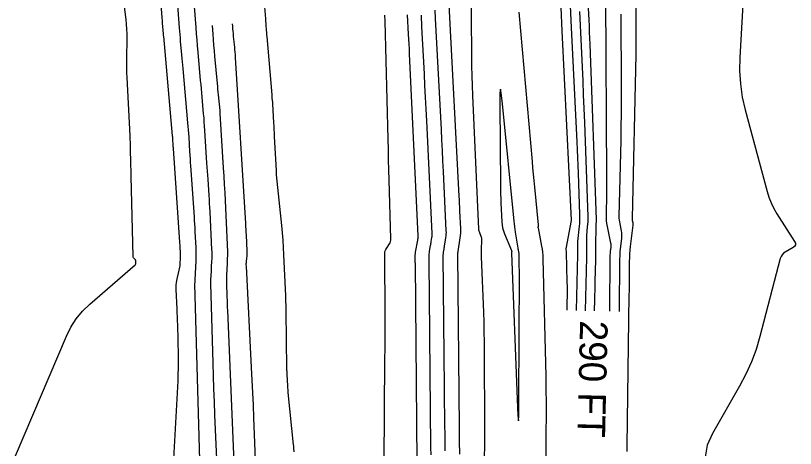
# Model space of a CAD drawing. Extents: x 1768942 to 1774819, y 723037 to 732099.
# Drawn here: x 1770723.5 to 1770892.8, y 725741.9 to 725835.9 of the extents above; entities that cross this region are included whole.
import ezdxf

# ---------------------------------------------------------------- set-up
doc = ezdxf.new("R2010")
doc.units = 0
doc.layers.add('R_Contour Annot', color=7, linetype='Continuous')
doc.layers.add('R_Contours', color=7, linetype='Continuous')

msp = doc.modelspace()

# ---------------------------------------------------------------- linework, layer by layer
at = {"layer": 'R_Contours'}
for points in [[(1770753.58, 725857.05), (1770755.22, 725835.49), (1770755.24, 725835.24), (1770755.26, 725834.98), (1770755.27, 725834.73), (1770755.29, 725834.48), (1770755.39, 725833.27), (1770755.4, 725833.11), (1770755.41, 725832.96), (1770755.42, 725832.8), (1770755.44, 725832.65), (1770755.49, 725832.03), (1770755.51, 725831.87), (1770755.52, 725831.72), (1770755.53, 725831.56), (1770755.55, 725831.41), (1770757.48, 725809.81), (1770757.5, 725809.58), (1770757.52, 725809.35), (1770757.53, 725809.12), (1770757.55, 725808.89), (1770757.6, 725807.98), (1770757.62, 725807.75), (1770757.63, 725807.52), (1770757.65, 725807.29), (1770757.66, 725807.06), (1770759.06, 725786.69), (1770759.08, 725786.41), (1770759.09, 725786.14), (1770759.11, 725785.86), (1770759.12, 725785.59), (1770759.18, 725784.48), (1770759.19, 725784.21), (1770759.19, 725783.93), (1770759.19, 725783.66), (1770759.18, 725783.38), (1770759.11, 725781.93), (1770759.09, 725781.6), (1770759.05, 725781.26), (1770759, 725780.94), (1770758.93, 725780.61), (1770758.41, 725778.38), (1770758.31, 725777.9), (1770758.25, 725777.42), (1770758.22, 725776.93), (1770758.23, 725776.44), (1770758.45, 725772.23), (1770758.49, 725771.36), (1770758.53, 725770.5), (1770758.56, 725769.63), (1770758.58, 725768.76), (1770758.74, 725762.14), (1770758.76, 725760.75), (1770758.76, 725759.36), (1770758.72, 725757.97), (1770758.66, 725756.58), (1770756.84, 725722.71)], [(1770723.45, 725740.31), (1770734.5, 725766.29), (1770735.47, 725768.26), (1770736.64, 725770.07), (1770738, 725771.74), (1770739.57, 725773.26), (1770749.42, 725781.82), (1770749.49, 725781.89), (1770749.54, 725781.98), (1770749.57, 725782.07), (1770749.58, 725782.18), (1770749.56, 725782.62), (1770749.55, 725782.72), (1770749.52, 725782.81), (1770749.47, 725782.89), (1770749.41, 725782.97), (1770749.11, 725783.27), (1770749.05, 725783.34), (1770749, 725783.43), (1770748.97, 725783.52), (1770748.96, 725783.62), (1770748.55, 725801.06), (1770748.53, 725801.78), (1770748.52, 725802.51), (1770748.5, 725803.24), (1770748.49, 725803.96), (1770748.44, 725806.87), (1770748.42, 725807.6), (1770748.4, 725808.32), (1770748.37, 725809.05), (1770748.33, 725809.77), (1770747.66, 725822.46), (1770747.61, 725823.51), (1770747.58, 725824.56), (1770747.58, 725825.61), (1770747.59, 725826.67), (1770747.66, 725830.87), (1770747.66, 725831.92), (1770747.63, 725832.97), (1770747.55, 725834.02), (1770747.44, 725835.06), (1770745.81, 725847.76)], [(1770761.6, 725846.21), (1770762.58, 725833.3), (1770762.68, 725831.97), (1770762.79, 725830.65), (1770762.9, 725829.32), (1770763.02, 725827.99), (1770763.57, 725821.84), (1770763.66, 725820.94), (1770763.74, 725820.03), (1770763.82, 725819.13), (1770763.9, 725818.22), (1770764.22, 725814.6), (1770764.3, 725813.69), (1770764.37, 725812.79), (1770764.44, 725811.88), (1770764.5, 725810.97), (1770764.95, 725803.87), (1770765, 725803), (1770765.06, 725802.12), (1770765.12, 725801.24), (1770765.18, 725800.36), (1770765.42, 725796.85), (1770765.48, 725795.97), (1770765.53, 725795.09), (1770765.58, 725794.21), (1770765.62, 725793.33), (1770766.03, 725785.02), (1770766.05, 725784.66), (1770766.05, 725784.31), (1770766.05, 725783.95), (1770766.04, 725783.59), (1770765.97, 725782.16), (1770765.95, 725781.8), (1770765.94, 725781.44), (1770765.92, 725781.09), (1770765.9, 725780.73), (1770765.82, 725779.22), (1770765.81, 725778.85), (1770765.8, 725778.48), (1770765.8, 725778.11), (1770765.81, 725777.74), (1770766.28, 725760.47), (1770766.36, 725757.66), (1770766.46, 725754.85), (1770766.56, 725752.04), (1770766.67, 725749.24), (1770767.15, 725738.01)], [(1770776.92, 725844.86), (1770777.71, 725835.23), (1770777.73, 725834.91), (1770777.76, 725834.59), (1770777.78, 725834.27), (1770777.81, 725833.95), (1770777.91, 725832.66), (1770777.93, 725832.34), (1770777.96, 725832.02), (1770777.98, 725831.7), (1770778.01, 725831.38), (1770779.08, 725818.71), (1770779.1, 725818.55), (1770779.11, 725818.38), (1770779.13, 725818.22), (1770779.14, 725818.06), (1770779.21, 725817.4), (1770779.23, 725817.24), (1770779.24, 725817.07), (1770779.25, 725816.91), (1770779.26, 725816.75), (1770779.47, 725812.64), (1770779.51, 725811.9), (1770779.55, 725811.16), (1770779.59, 725810.42), (1770779.62, 725809.68), (1770780.01, 725802.25), (1770780.01, 725802.17), (1770780.02, 725802.09), (1770780.02, 725802.01), (1770780.03, 725801.94), (1770780.05, 725801.63), (1770780.06, 725801.55), (1770780.06, 725801.47), (1770780.07, 725801.39), (1770780.08, 725801.31), (1770781.21, 725790.31), (1770781.36, 725788.73), (1770781.49, 725787.16), (1770781.59, 725785.58), (1770781.67, 725784), (1770782.05, 725775.08), (1770782.06, 725774.81), (1770782.07, 725774.53), (1770782.09, 725774.25), (1770782.1, 725773.97), (1770782.15, 725772.86), (1770782.16, 725772.58), (1770782.17, 725772.3), (1770782.18, 725772.03), (1770782.18, 725771.75), (1770782.31, 725759.3), (1770782.31, 725759.1), (1770782.32, 725758.9), (1770782.33, 725758.7), (1770782.34, 725758.5), (1770782.38, 725757.7), (1770782.39, 725757.5), (1770782.4, 725757.3), (1770782.41, 725757.1), (1770782.42, 725756.9), (1770782.51, 725755.36), (1770782.53, 725755.03), (1770782.55, 725754.71), (1770782.58, 725754.39), (1770782.61, 725754.06), (1770783.77, 725742.74), (1770783.79, 725742.54), (1770783.81, 725742.35), (1770783.83, 725742.15), (1770783.84, 725741.96), (1770783.9, 725741.17)], [(1770758.54, 725839.08), (1770758.98, 725833.28), (1770759.04, 725832.54), (1770759.1, 725831.8), (1770759.16, 725831.06), (1770759.23, 725830.32), (1770759.5, 725827.36), (1770759.56, 725826.62), (1770759.63, 725825.88), (1770759.7, 725825.14), (1770759.76, 725824.39), (1770760.81, 725812.63), (1770760.88, 725811.85), (1770760.94, 725811.07), (1770761, 725810.29), (1770761.05, 725809.51), (1770761.25, 725806.38), (1770761.3, 725805.6), (1770761.35, 725804.82), (1770761.4, 725804.04), (1770761.45, 725803.26), (1770762.21, 725792.24), (1770762.26, 725791.42), (1770762.31, 725790.61), (1770762.36, 725789.8), (1770762.4, 725788.99), (1770762.57, 725785.55), (1770762.59, 725784.83), (1770762.6, 725784.12), (1770762.6, 725783.4), (1770762.57, 725782.69), (1770762.38, 725778.55), (1770762.38, 725778.47), (1770762.37, 725778.4), (1770762.37, 725778.32), (1770762.36, 725778.24), (1770762.35, 725777.93), (1770762.35, 725777.85), (1770762.34, 725777.77), (1770762.34, 725777.69), (1770762.34, 725777.62), (1770763.47, 725736.84)], [(1770847.68, 725840.23), (1770847.93, 725834.97), (1770848, 725833.66), (1770848.05, 725832.34), (1770848.11, 725831.03), (1770848.16, 725829.71), (1770849.53, 725791.65), (1770849.54, 725791.53), (1770849.54, 725791.41), (1770849.53, 725791.29), (1770849.52, 725791.17), (1770849.47, 725790.69), (1770849.46, 725790.57), (1770849.45, 725790.45), (1770849.45, 725790.33), (1770849.45, 725790.21), (1770849.42, 725785.86), (1770849.42, 725785.09), (1770849.41, 725784.33), (1770849.4, 725783.56), (1770849.39, 725782.8), (1770849.29, 725778.23), (1770849.27, 725777.21), (1770849.25, 725776.19), (1770849.22, 725775.18), (1770849.19, 725774.16), (1770849.11, 725771.79)], [(1770852.52, 725771.71), (1770852.62, 725783.76), (1770852.62, 725783.99), (1770852.63, 725784.22), (1770852.65, 725784.45), (1770852.67, 725784.68), (1770852.78, 725785.6), (1770852.8, 725785.83), (1770852.8, 725786.06), (1770852.78, 725786.29), (1770852.74, 725786.52), (1770852, 725790.1), (1770851.88, 725790.77), (1770851.8, 725791.45), (1770851.76, 725792.13), (1770851.76, 725792.81), (1770851.85, 725796.99), (1770851.87, 725797.92), (1770851.88, 725798.84), (1770851.88, 725799.77), (1770851.88, 725800.69), (1770851.63, 725839.98)], [(1770856.3, 725741.24), (1770856.31, 725742.51), (1770856.75, 725775.3), (1770856.76, 725776.18), (1770856.77, 725777.06), (1770856.78, 725777.95), (1770856.79, 725778.83), (1770856.82, 725782.49), (1770856.83, 725783.31), (1770856.87, 725784.13), (1770856.94, 725784.95), (1770857.02, 725785.77), (1770857.57, 725790.43), (1770857.57, 725790.55), (1770857.57, 725790.66), (1770857.56, 725790.78), (1770857.55, 725790.89), (1770857.45, 725791.36), (1770857.43, 725791.47), (1770857.42, 725791.59), (1770857.41, 725791.7), (1770857.41, 725791.82), (1770858.22, 725827.47), (1770858.25, 725828.92), (1770858.27, 725830.36), (1770858.27, 725831.81), (1770858.27, 725833.26), (1770858.23, 725839.04)], [(1770817.56, 725838.27), (1770819.74, 725796.68), (1770819.78, 725795.88), (1770819.82, 725795.08), (1770819.86, 725794.28), (1770819.9, 725793.48), (1770820.08, 725789.7), (1770820.09, 725789.19), (1770820.08, 725788.68), (1770820.04, 725788.17), (1770819.97, 725787.66), (1770819.5, 725784.7), (1770819.49, 725784.66), (1770819.48, 725784.61), (1770819.48, 725784.57), (1770819.47, 725784.52), (1770819.44, 725784.34), (1770819.43, 725784.3), (1770819.42, 725784.25), (1770819.42, 725784.21), (1770819.42, 725784.16), (1770819.78, 725746.38), (1770819.79, 725745.67), (1770819.79, 725744.95), (1770819.8, 725744.24), (1770819.81, 725743.53), (1770819.84, 725740.67)], [(1770825.31, 725739.54), (1770825.35, 725743), (1770825.35, 725746.46), (1770825.3, 725762.95), (1770825.29, 725765.09), (1770825.25, 725767.23), (1770825.2, 725769.37), (1770825.13, 725771.5), (1770824.67, 725783.52), (1770824.66, 725783.92), (1770824.65, 725784.33), (1770824.66, 725784.73), (1770824.67, 725785.13), (1770824.74, 725787.13), (1770824.74, 725787.34), (1770824.71, 725787.55), (1770824.66, 725787.75), (1770824.59, 725787.95), (1770824.27, 725788.73), (1770824.19, 725788.93), (1770824.14, 725789.13), (1770824.1, 725789.34), (1770824.08, 725789.55), (1770822.77, 725818.59), (1770822.68, 725820.72), (1770822.62, 725822.86), (1770822.57, 725825), (1770822.54, 725827.14), (1770822.47, 725835.7), (1770822.45, 725837.84)], [(1770843.24, 725771.93), (1770843.28, 725773.81), (1770843.3, 725774.89), (1770843.3, 725775.97), (1770843.29, 725777.05), (1770843.27, 725778.12), (1770843.12, 725784.44), (1770843.12, 725784.51), (1770843.11, 725784.59), (1770843.1, 725784.66), (1770843.09, 725784.73), (1770843.04, 725785.02), (1770843.03, 725785.09), (1770843.02, 725785.16), (1770843.03, 725785.23), (1770843.04, 725785.3), (1770844.19, 725791.43), (1770844.2, 725791.44), (1770844.2, 725791.44), (1770844.2, 725791.45), (1770844.2, 725791.46), (1770844.19, 725791.49), (1770844.19, 725791.5), (1770844.19, 725791.5), (1770844.2, 725791.51), (1770844.2, 725791.52), (1770844.2, 725791.52), (1770842.2, 725832.62), (1770841.94, 725837.63)], [(1770843.88, 725838), (1770844.11, 725833.3), (1770845.32, 725808.48), (1770845.4, 725806.78), (1770845.48, 725805.07), (1770845.55, 725803.37), (1770845.61, 725801.66), (1770845.94, 725792.7), (1770845.95, 725792.07), (1770845.94, 725791.44), (1770845.91, 725790.8), (1770845.86, 725790.17), (1770845.53, 725786.85), (1770845.5, 725786.62), (1770845.49, 725786.39), (1770845.48, 725786.15), (1770845.48, 725785.92), (1770845.47, 725784.98), (1770845.47, 725784.75), (1770845.47, 725784.51), (1770845.46, 725784.28), (1770845.46, 725784.05), (1770845.22, 725771.88)], [(1770881.43, 725838.33), (1770880.76, 725826.79), (1770880.71, 725823.91), (1770880.89, 725821.06), (1770881.29, 725818.23), (1770881.93, 725815.43), (1770886.67, 725797.75), (1770887.07, 725796.47), (1770887.56, 725795.23), (1770888.14, 725794.03), (1770888.82, 725792.87), (1770892.64, 725786.86), (1770892.82, 725786.47), (1770892.82, 725786.12), (1770892.66, 725785.81), (1770892.32, 725785.55), (1770890.63, 725784.57), (1770890.25, 725784.3), (1770889.94, 725783.97), (1770889.7, 725783.58), (1770889.54, 725783.14), (1770885.12, 725766.26), (1770884.28, 725763.44), (1770883.26, 725760.7), (1770882.06, 725758.03), (1770880.68, 725755.44), (1770874.79, 725745.2), (1770873.66, 725742.64), (1770873.24, 725740.05)], [(1770803.47, 725738.83), (1770803.68, 725761.31), (1770803.7, 725763.66), (1770803.71, 725766.02), (1770803.71, 725768.37), (1770803.7, 725770.73), (1770803.65, 725784.28), (1770803.67, 725784.57), (1770803.73, 725784.84), (1770803.84, 725785.1), (1770803.98, 725785.35), (1770804.65, 725786.33), (1770804.8, 725786.58), (1770804.9, 725786.84), (1770804.96, 725787.12), (1770804.97, 725787.41), (1770804.6, 725800.17), (1770804.53, 725802.39), (1770804.47, 725804.62), (1770804.41, 725806.84), (1770804.35, 725809.07), (1770803.7, 725834.66), (1770803.66, 725835.99)], [(1770808.52, 725836.1), (1770808.74, 725831.85), (1770808.79, 725830.78), (1770808.85, 725829.72), (1770808.9, 725828.66), (1770808.95, 725827.59), (1770810.85, 725788.06), (1770810.85, 725787.99), (1770810.85, 725787.91), (1770810.84, 725787.83), (1770810.83, 725787.76), (1770810.78, 725787.45), (1770810.77, 725787.37), (1770810.76, 725787.3), (1770810.74, 725787.22), (1770810.73, 725787.14), (1770810.26, 725784.51), (1770810.23, 725784.31), (1770810.21, 725784.12), (1770810.19, 725783.93), (1770810.19, 725783.73), (1770810.2, 725782.95), (1770810.2, 725782.76), (1770810.2, 725782.56), (1770810.2, 725782.37), (1770810.21, 725782.17), (1770810.63, 725738.93)], [(1770813.69, 725740.54), (1770813.67, 725742.17), (1770813.43, 725766.49), (1770813.42, 725768.26), (1770813.4, 725770.03), (1770813.38, 725771.79), (1770813.37, 725773.56), (1770813.27, 725783.6), (1770813.27, 725783.88), (1770813.29, 725784.16), (1770813.32, 725784.44), (1770813.36, 725784.73), (1770813.59, 725785.96), (1770813.63, 725786.18), (1770813.66, 725786.4), (1770813.7, 725786.62), (1770813.74, 725786.84), (1770813.88, 725787.72), (1770813.91, 725787.94), (1770813.92, 725788.17), (1770813.93, 725788.39), (1770813.93, 725788.61), (1770812.75, 725813.08), (1770812.63, 725815.62), (1770812.5, 725818.17), (1770812.37, 725820.72), (1770812.24, 725823.27), (1770811.71, 725833.46), (1770811.58, 725836.01)], [(1770816.76, 725741.38), (1770816.73, 725743.68), (1770816.64, 725752.89), (1770816.62, 725755.19), (1770816.6, 725757.49), (1770816.57, 725759.79), (1770816.55, 725762.09), (1770816.35, 725783.88), (1770816.35, 725784.04), (1770816.36, 725784.21), (1770816.37, 725784.37), (1770816.4, 725784.53), (1770816.52, 725785.18), (1770816.54, 725785.34), (1770816.57, 725785.51), (1770816.6, 725785.67), (1770816.63, 725785.83), (1770816.92, 725787.69), (1770816.97, 725788.06), (1770817, 725788.42), (1770817.01, 725788.79), (1770817, 725789.16), (1770816.38, 725802.07), (1770816.27, 725804.35), (1770816.16, 725806.63), (1770816.05, 725808.9), (1770815.93, 725811.18), (1770814.67, 725835.24), (1770814.57, 725837.07)], [(1770832.74, 725836.68), (1770835.63, 725804.22), (1770835.75, 725802.83), (1770835.88, 725801.45), (1770836.01, 725800.07), (1770836.15, 725798.69), (1770836.97, 725790.51), (1770836.98, 725790.45), (1770836.98, 725790.4), (1770836.97, 725790.34), (1770836.96, 725790.28), (1770836.92, 725790.05), (1770836.91, 725789.99), (1770836.91, 725789.93), (1770836.91, 725789.88), (1770836.92, 725789.82), (1770837.69, 725785.87), (1770837.81, 725785.19), (1770837.9, 725784.51), (1770837.96, 725783.82), (1770837.99, 725783.13), (1770838.59, 725757.59), (1770838.62, 725755.85), (1770838.65, 725754.12), (1770838.66, 725752.39), (1770838.66, 725750.65), (1770838.64, 725743.72), (1770838.64, 725741.98), (1770838.64, 725740.25)], [(1770845.9, 725836.76), (1770846.48, 725824.73), (1770846.62, 725821.72), (1770846.76, 725818.71), (1770846.88, 725815.7), (1770846.99, 725812.69), (1770847.74, 725792.18), (1770847.74, 725791.8), (1770847.74, 725791.42), (1770847.72, 725791.05), (1770847.69, 725790.67), (1770847.54, 725789.17), (1770847.5, 725788.79), (1770847.48, 725788.42), (1770847.47, 725788.04), (1770847.46, 725787.66), (1770847.45, 725785.42), (1770847.44, 725784.92), (1770847.44, 725784.42), (1770847.43, 725783.92), (1770847.42, 725783.42), (1770847.19, 725771.84)], [(1770854.62, 725771.67), (1770854.72, 725783.13), (1770854.73, 725783.65), (1770854.75, 725784.18), (1770854.79, 725784.7), (1770854.85, 725785.22), (1770855.12, 725787.56), (1770855.15, 725787.96), (1770855.15, 725788.36), (1770855.12, 725788.76), (1770855.05, 725789.15), (1770854.73, 725790.73), (1770854.66, 725791.12), (1770854.61, 725791.52), (1770854.58, 725791.92), (1770854.58, 725792.32), (1770854.96, 725808.83), (1770855.01, 725811.72), (1770855.05, 725814.6), (1770855.06, 725817.49), (1770855.05, 725820.38), (1770854.95, 725836.18)], [(1770775.63, 725737.63), (1770775.2, 725748.57), (1770775.09, 725751.3), (1770774.97, 725754.03), (1770774.84, 725756.76), (1770774.7, 725759.5), (1770773.57, 725781.49), (1770773.56, 725781.77), (1770773.56, 725782.05), (1770773.57, 725782.33), (1770773.6, 725782.61), (1770773.72, 725783.73), (1770773.74, 725784.01), (1770773.76, 725784.29), (1770773.76, 725784.57), (1770773.75, 725784.85), (1770773.59, 725788.23), (1770773.56, 725788.86), (1770773.53, 725789.5), (1770773.49, 725790.13), (1770773.45, 725790.76), (1770771.22, 725826.78), (1770771.18, 725827.35), (1770771.14, 725827.93), (1770771.09, 725828.5), (1770771.04, 725829.07), (1770770.81, 725831.35), (1770770.76, 725831.92), (1770770.71, 725832.49), (1770770.66, 725833.06), (1770770.62, 725833.63), (1770770.58, 725834.12)], [(1770766.13, 725833.79), (1770766.28, 725831.89), (1770766.37, 725830.69), (1770766.47, 725829.49), (1770766.57, 725828.29), (1770766.68, 725827.1), (1770767.22, 725821.16), (1770767.27, 725820.54), (1770767.33, 725819.92), (1770767.39, 725819.31), (1770767.45, 725818.69), (1770767.78, 725815.32), (1770767.8, 725815.15), (1770767.81, 725814.98), (1770767.83, 725814.81), (1770767.84, 725814.64), (1770768.57, 725802.86), (1770768.68, 725801.06), (1770768.78, 725799.26), (1770768.87, 725797.47), (1770768.96, 725795.67), (1770769.5, 725784.6), (1770769.5, 725784.55), (1770769.5, 725784.49), (1770769.3, 725780.52), (1770769.27, 725779.85), (1770769.26, 725779.19), (1770769.26, 725778.53), (1770769.27, 725777.86), (1770769.35, 725774.81), (1770769.37, 725774.08), (1770769.4, 725773.35), (1770769.42, 725772.62), (1770769.45, 725771.89), (1770771.13, 725732.01)]]:
    msp.add_lwpolyline(points, dxfattribs=at)
msp.add_lwpolyline([(1770831.19, 725784.47), (1770831.19, 725784.42), (1770831.19, 725784.37), (1770831.19, 725784.32), (1770832.4, 725752.62), (1770832.55, 725749.1), (1770832.67, 725747.93), (1770832.75, 725749.1), (1770832.78, 725752.62), (1770832.87, 725779.87), (1770832.87, 725780.33), (1770832.87, 725780.79), (1770832.86, 725781.24), (1770832.85, 725781.7), (1770832.79, 725784.25), (1770832.79, 725784.35), (1770832.78, 725784.44), (1770832.77, 725784.54), (1770832.75, 725784.63), (1770832.68, 725785), (1770832.66, 725785.1), (1770832.64, 725785.19), (1770832.63, 725785.29), (1770832.61, 725785.38), (1770832.06, 725788.85), (1770831.96, 725789.46), (1770831.88, 725790.07), (1770831.81, 725790.69), (1770831.74, 725791.3), (1770829.21, 725816.72), (1770828.93, 725819.15), (1770828.74, 725819.95), (1770828.64, 725819.13), (1770828.62, 725816.68), (1770828.76, 725798.95), (1770828.78, 725798.03), (1770828.8, 725797.12), (1770828.82, 725796.21), (1770828.86, 725795.29), (1770829.05, 725791.16), (1770829.11, 725790.49), (1770829.22, 725789.84), (1770829.4, 725789.19), (1770829.63, 725788.56), (1770831.16, 725784.9), (1770831.18, 725784.85), (1770831.19, 725784.81), (1770831.2, 725784.76), (1770831.2, 725784.71), (1770831.19, 725784.52)], close=True, dxfattribs=at)

# ---------------------------------------------------------------- texts
at = {"layer": 'R_Contour Annot'}
msp.add_text('290 FT', height=6, rotation=268.6654, dxfattribs=at).set_placement((1770846.07, 725769.76))

doc.saveas('drawing.dxf')
